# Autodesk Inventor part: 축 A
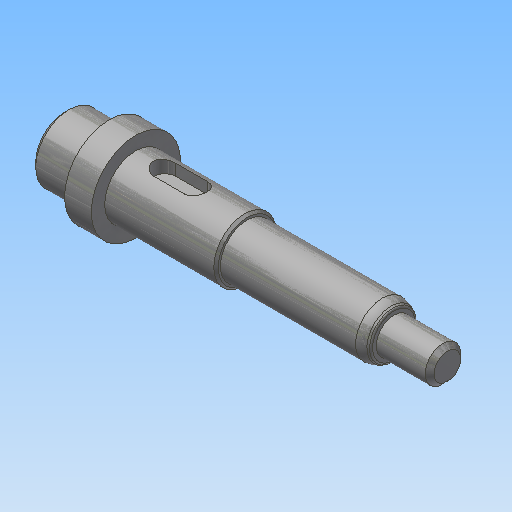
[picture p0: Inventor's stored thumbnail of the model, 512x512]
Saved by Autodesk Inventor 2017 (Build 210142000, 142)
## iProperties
Created: 2020-04
Part Number: 축 A
Material: 강철, 연강
Document SubType Name: Modeling
Designer: mduedu
Density: 7.86 g/cm^3
Mass: 91.1355 g
Surface Area: 41.2026 cm^2
Volume: 11.5948 cm^3
Appearance: 강철
Author: mduedu
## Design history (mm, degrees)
sketch "스케치1"
  geometry: L1 (0, 0)-(10, 0); L2 (10, 0)-(10, 7.5); L3 (10, 7.5)-(0, 7.5); L4 (0, 7.5)-(0, 0); L5 (10, 0)-(16, 0); L6 (16, 0)-(16, 10); L7 (16, 10)-(10, 10); L8 (10, 10)-(10, 0); L9 (16, 0)-(41, 0); L10 (41, 0)-(41, 7); L11 (41, 7)-(16, 7); L12 (16, 7)-(16, 0); L13 (41, 0)-(74, 0); L14 (74, 0)-(74, 6); L15 (74, 6)-(41, 6); L16 (41, 6)-(41, 0); L17 (74, 0)-(86, 0); L18 (86, 0)-(86, 4); L19 (86, 4)-(74, 4); L20 (74, 4)-(74, 0)
  constraints: 40 end point, 10 parallel, 5 horizontal, 5 perpendicular
  dimensions: "d0" = 86 distance between parallel lines of L18 L4; "d2" = 10 distance of L2.end L3.end; "d3" = 6 distance of L6.end L7.end; "d4" = 12 distance of L18.end L19.end; "d5" = 8 diameter of L19 L17; "d6" = 12 diameter of L15 L13; "d7" = 14 diameter of L11 L9; "d8" = 15 diameter of L3 L1; "d9" = 20 diameter of L7 L5; "d10" = 45 distance between parallel lines of L10 L18
revolve "회전1" sketch "스케치1" stored, may be unused: angle "d11" = 90 deg
sketch "스케치2"
  geometry: L1 (0, -7.5)-(0, 7.5) reference; L2 (0, 7.5)-(10, 7.5) reference; L3 (10, 7.5)-(10, 10) reference; L4 (10, 10)-(16, 10) reference; L5 (16, 10)-(16, 7) reference; L6 (16, 7)-(41, 7) reference; L7 (41, 7)-(41, 6) reference; L8 (41, 6)-(74, 6) reference; L9 (74, 6)-(74, 4) reference; L10 (74, 4)-(86, 4) reference; L11 (86, 4)-(86, -4) reference; L12 (86, -4)-(74, -4) reference; L13 (74, -4)-(74, -6) reference; L14 (74, -6)-(41, -6) reference; L15 (41, -6)-(41, -7) reference; L16 (41, -7)-(16, -7) reference; L17 (16, -7)-(16, -10) reference; L18 (16, -10)-(10, -10) reference; L19 (10, -10)-(10, -7.5) reference; L20 (10, -7.5)-(0, -7.5) reference; L21 (86, -4)-(78, -4); L22 (78, -4)-(78, -2.8); L23 (78, -2.8)-(86, -2.8); L24 (86, -2.8)-(86, -4); 1 further point
  constraints: 8 end point, 2 parallel, 1 horizontal, 1 perpendicular
  dimensions: "d12" = 8 distance of L22.end L23.end; "d13" = 1.2 distance of L21.end L22.end
extrude "돌출1" cut sketch "스케치2" stored distance "d14" = 2; taper "d15" = 0 deg
fillet "모깎기1" dims "d16" = 1
sketch "스케치3"
  geometry: L1 (0, -7.5)-(0, 7.5) reference; L2 (0, 7.5)-(10, 7.5) reference; L3 (10, 7.5)-(10, 10) reference; L4 (10, 10)-(16, 10) reference; L5 (16, 10)-(16, 7) reference; L6 (16, 7)-(41, 7) reference; L7 (41, 7)-(41, 6) reference; L8 (41, 6)-(74, 6) reference; L9 (74, 6)-(74, 4) reference; L10 (74, 4)-(86, 4) reference; L11 (86, 4)-(86, -2.8) reference; L12 (86, -2.8)-(78, -2.8) reference; L13 (78, -2.8)-(78, -4) reference; L14 (78, -4)-(74, -4) reference; L15 (74, -4)-(74, -6) reference; L16 (74, -6)-(41, -6) reference; L17 (41, -6)-(41, -7) reference; L18 (41, -7)-(16, -7) reference; L19 (16, -7)-(16, -10) reference; L20 (16, -10)-(10, -10) reference; L21 (10, -10)-(10, -7.5) reference; L22 (10, -7.5)-(0, -7.5) reference; L23 (20, 7)-(32, 7); L24 (32, 7)-(32, 4); L25 (32, 4)-(20, 4); L26 (20, 4)-(20, 7); 1 further point
  constraints: 8 end point, 2 parallel, 1 horizontal, 1 perpendicular, 1 point on line
  dimensions: "d17" = 12 distance of L24.end L25.end; "d18" = 3 distance of L23.end L24.end; "d19" = 4 distance from line of L26 L4.end
extrude "돌출2" cut sketch "스케치3" stored distance "d20" = 5; taper "d21" = 0 deg
fillet "모깎기2" dims "d22" = 2.5
chamfer "모따기1" distance "d23" = 1; stored, may be unused: second distance "d24" = 2, angle "d25" = 45 deg
chamfer "모따기2" distance "d26" = 0.5; stored, may be unused: second distance "d27" = 2, angle "d28" = 45 deg
fillet "모깎기3" dims "d29" = 0.3
chamfer "모따기3" distance "d30" = 1.56; stored, may be unused: second distance "d31" = 2, angle "d32" = 30 deg
fillet "모깎기4" dims "d33" = 4, "d34" = 0.5
node "솔리드1"
node "절단 모서리 투영1"
node "절단 모서리 투영2"
